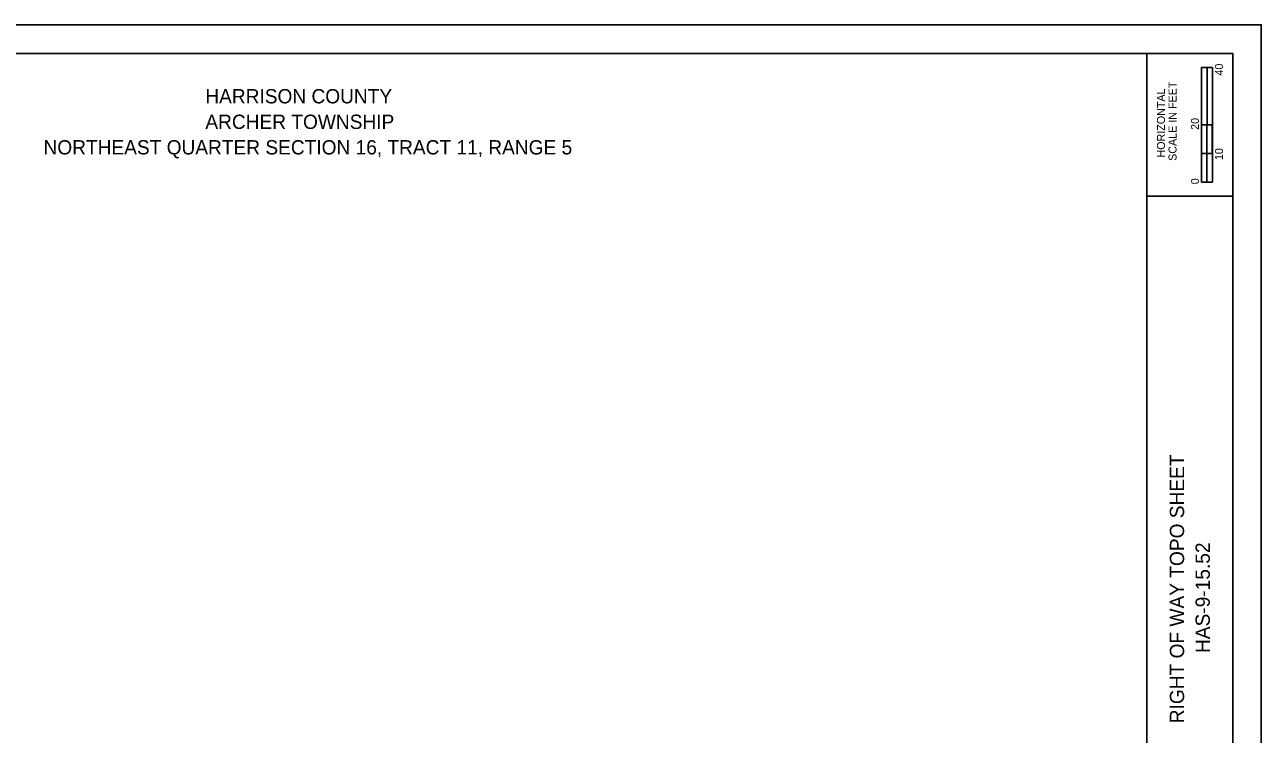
# Model space of a CAD drawing. Extents: x -1.6 to 34, y 0 to 22.
# Drawn here: x 12.36 to 34, y 9.59 to 22 of the extents above; entities that cross this region are included whole.
import ezdxf

# ---------------------------------------------------------------- set-up
doc = ezdxf.new("R2010")
doc.units = 0
for name, color, linetype in [('SH_Border', 7, 'Continuous'), ('SH_Cut_Line', 7, 'Continuous'), ('SH_Data', 7, 'Continuous')]:
    doc.layers.add(name, color=color, linetype=linetype)

msp = doc.modelspace()

# ---------------------------------------------------------------- linework, layer by layer
at = {"layer": 'SH_Border'}
for p, q in [((32, 0.5), (32, 21.5)), ((32, 19), (33.5, 19))]:
    msp.add_line(p, q, dxfattribs=at)
msp.add_lwpolyline([(1.5, 21.5), (33.5, 21.5), (33.5, 0.5), (1.5, 0.5)], close=True, dxfattribs=at)
at = {"layer": 'SH_Cut_Line'}
msp.add_lwpolyline([(0, 0), (34, 0), (34, 22), (0, 22)], close=True, dxfattribs=at)
at = {"layer": 'SH_Data'}
for p, q in [((32.957, 19.25), (32.957, 21.25)), ((33.144, 21.25), (32.957, 21.25)), ((32.957, 20.25), (32.957, 21.25)), ((32.957, 21.25), (33.05, 21.25)), ((33.05, 21.25), (33.051, 21.25)), ((33.051, 21.25), (33.051, 20.25)), ((33.144, 21.25), (33.144, 19.25)), ((33.051, 20.25), (32.957, 20.25)), ((33.143, 20.25), (33.05, 20.25)), ((33.05, 20.25), (33.05, 19.75)), ((33.143, 19.75), (33.143, 20.25)), ((33.05, 19.75), (32.957, 19.75)), ((32.957, 19.75), (32.957, 19.25)), ((33.05, 19.25), (33.05, 19.75)), ((33.05, 19.75), (33.143, 19.75)), ((33.144, 19.25), (32.957, 19.25)), ((32.957, 19.25), (33.05, 19.25))]:
    msp.add_line(p, q, dxfattribs=at)

# ---------------------------------------------------------------- texts
for s, height, p in [('40', 0.14, (33.33, 21.112)), ('SCALE IN FEET', 0.14, (32.517, 19.621)), ('HORIZONTAL', 0.14, (32.315, 19.679)), ('20', 0.14, (32.91, 20.162)), ('10', 0.14, (33.33, 19.633)), ('0', 0.14, (32.91, 19.211)), ('RIGHT OF WAY TOPO SHEET', 0.25, (32.65, 9.787)), ('HAS-9-15.52', 0.25, (33.1, 11.015))]:
    msp.add_text(s, height=height, rotation=90, dxfattribs=at).set_placement(p)
for s, p in [('HARRISON COUNTY', (15.523, 20.625)), ('ARCHER TOWNSHIP', (15.524, 20.178)), ('NORTHEAST QUARTER SECTION 16, TRACT 11, RANGE 5 ', (12.692, 19.732))]:
    msp.add_text(s, height=0.25, dxfattribs=at).set_placement(p)

doc.saveas('drawing.dxf')
